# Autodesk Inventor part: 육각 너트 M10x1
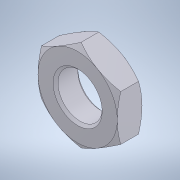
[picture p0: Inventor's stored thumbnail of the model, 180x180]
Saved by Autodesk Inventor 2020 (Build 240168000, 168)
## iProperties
Created: 2024-04
Part Number: 육각 너트 M10x1
Material: 강철, 연강
Description: 6각 가는 너트 - 이중 모따기(부품 등급 A) - 정밀 나사산
Document SubType Name: Modeling
Designer: oem
Density: 7.85 g/cm^3
Appearance: 기본값
Author: jhkim
Sending System: Autodesk Inventor 2025
Preprocessor: ST-DEVELOPER v20
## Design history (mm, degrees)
feature "Solid1"
node "솔리드1"
